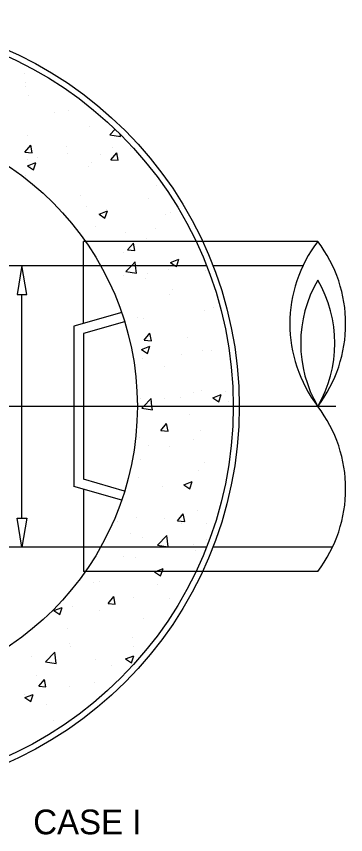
# Model space of a CAD drawing. Extents: x 6712067 to 6713867, y 1867712 to 1869162.
# Drawn here: x 6712343.8 to 6712423.9, y 1867918.1 to 1868116.9 of the extents above; entities that cross this region are included whole.
import ezdxf

# ---------------------------------------------------------------- set-up
doc = ezdxf.new("R2010")
doc.units = 0
for name, color, linetype in [('G-MARK', 7, 'Continuous'), ('G-TEXT', 7, 'Continuous'), ('Misc CnstDet(22)', 7, 'Continuous')]:
    doc.layers.add(name, color=color, linetype=linetype)

msp = doc.modelspace()

# ---------------------------------------------------------------- linework, layer by layer
at = {"layer": 'G-MARK'}
msp.add_line((6712345.2, 1867994.97), (6712345.2, 1868049.33), dxfattribs=at)
at = {"layer": 'G-TEXT'}
for points in [[(6712344.03, 1868049.33), (6712346.36, 1868049.33), (6712345.2, 1868056.33)], [(6712344.03, 1867994.97), (6712346.36, 1867994.97), (6712345.2, 1867987.98)]]:
    msp.add_lwpolyline(points, close=True, dxfattribs=at)
at = {"layer": 'Misc CnstDet(22)'}
for p, q in [((6712345.77, 1868103.12), (6712345.77, 1868103.12)), ((6712346.17, 1868100.93), (6712346.17, 1868100.93)), ((6712346.09, 1868099.86), (6712346.09, 1868099.86)), ((6712346.86, 1868097.56), (6712346.86, 1868097.56)), ((6712353.08, 1868093.46), (6712353.08, 1868093.46)), ((6712356.51, 1868094.06), (6712356.51, 1868094.06)), ((6712361.66, 1868090.04), (6712361.66, 1868090.04)), ((6712366.58, 1868088.11), (6712367.86, 1868089.46)), ((6712369.17, 1868087.71), (6712369.1, 1868088.25)), ((6712346.51, 1868087.86), (6712346.51, 1868087.86)), ((6712366.58, 1868088.11), (6712369.17, 1868087.71)), ((6712345.92, 1868083.89), (6712347.33, 1868085.57)), ((6712347.67, 1868083.74), (6712347.33, 1868085.57)), ((6712356.06, 1868085.38), (6712356.06, 1868085.38)), ((6712367.19, 1868084.97), (6712367.19, 1868084.97)), ((6712371.62, 1868084.73), (6712371.62, 1868084.73)), ((6712345.92, 1868083.89), (6712347.67, 1868083.74)), ((6712348.85, 1868082.56), (6712348.85, 1868082.56)), ((6712356.15, 1868083.51), (6712356.15, 1868083.51)), ((6712364.21, 1868083.26), (6712364.21, 1868083.26)), ((6712366.83, 1868082.07), (6712368.24, 1868083.74)), ((6712368.58, 1868081.92), (6712368.23, 1868083.74)), ((6712346.53, 1868080.56), (6712348.57, 1868081.35)), ((6712346.53, 1868080.56), (6712347.98, 1868079.59)), ((6712346.65, 1868082.12), (6712346.65, 1868082.12)), ((6712347.21, 1868080.34), (6712347.21, 1868080.34)), ((6712347.98, 1868079.59), (6712348.57, 1868081.34)), ((6712361.3, 1868080.34), (6712361.3, 1868080.34)), ((6712362.21, 1868081.47), (6712362.21, 1868081.47)), ((6712366.83, 1868082.07), (6712368.58, 1868081.92)), ((6712346.15, 1868078.15), (6712346.15, 1868078.15)), ((6712377.93, 1868075.9), (6712377.93, 1868075.9)), ((6712359.52, 1868073.47), (6712359.52, 1868073.47)), ((6712375.91, 1868072.69), (6712375.91, 1868072.69)), ((6712360.94, 1868070.64), (6712360.94, 1868070.64)), ((6712363.93, 1868068.83), (6712365.97, 1868069.61)), ((6712363.93, 1868068.83), (6712365.37, 1868067.85)), ((6712365.37, 1868067.85), (6712365.97, 1868069.61)), ((6712365.82, 1868069.91), (6712365.82, 1868069.91)), ((6712380.01, 1868068.79), (6712380.01, 1868068.79)), ((6712381.38, 1868069.25), (6712381.38, 1868069.25)), ((6712363.01, 1868065.87), (6712363.01, 1868065.87)), ((6712370.26, 1868064.4), (6712370.26, 1868064.4)), ((6712377.55, 1868065.36), (6712377.55, 1868065.36)), ((6712375.55, 1868062.98), (6712375.55, 1868062.98)), ((6712386.99, 1868062.38), (6712386.99, 1868062.38)), ((6712360.13, 1868042.27), (6712360.13, 1868062.22)), ((6712389.13, 1868062.22), (6712360.13, 1868062.22)), ((6712370.87, 1868060.15), (6712372.28, 1868061.81)), ((6712372.62, 1868059.99), (6712372.28, 1868061.81)), ((6712417.12, 1868062.22), (6712389.13, 1868062.22)), ((6712369.99, 1868059.47), (6712369.99, 1868059.47)), ((6712370.87, 1868060.15), (6712372.62, 1868059.99)), ((6712371.81, 1868056.32), (6712372.72, 1868057.27)), ((6712372.82, 1868056.32), (6712372.71, 1868057.27)), ((6712381.33, 1868057.09), (6712383.37, 1868057.87)), ((6712381.33, 1868057.09), (6712382.46, 1868056.32)), ((6712382.85, 1868056.32), (6712383.37, 1868057.87)), ((6712364.34, 1868056.32), (6712242.25, 1868056.32)), ((6712345.2, 1868056.33), (6712345.2, 1868056.33)), ((6712345.2, 1868056.33), (6712345.2, 1868056.33)), ((6712390.08, 1868056.32), (6712364.34, 1868056.32)), ((6712370.45, 1868054.9), (6712371.81, 1868056.32)), ((6712370.45, 1868054.9), (6712373.04, 1868054.5)), ((6712373.04, 1868054.49), (6712372.82, 1868056.32)), ((6712380.92, 1868055.31), (6712380.92, 1868055.31)), ((6712382.46, 1868056.32), (6712382.78, 1868056.12)), ((6712382.77, 1868056.12), (6712382.85, 1868056.32)), ((6712389.92, 1868055.14), (6712389.92, 1868055.14)), ((6712413.53, 1868056.32), (6712391.65, 1868056.32)), ((6712369.88, 1868053.87), (6712369.88, 1868053.87)), ((6712375.2, 1868053.28), (6712375.2, 1868053.28)), ((6712375.7, 1868054.35), (6712375.7, 1868054.35)), ((6712381.85, 1868050.44), (6712381.85, 1868050.44)), ((6712381.12, 1868049.27), (6712381.12, 1868049.27)), ((6712369.44, 1868044.93), (6712357.8, 1868041.6)), ((6712389.57, 1868045.45), (6712389.57, 1868045.45)), ((6712391.67, 1868046.25), (6712391.67, 1868046.25)), ((6712370.16, 1868042.71), (6712360.14, 1868039.85)), ((6712373.26, 1868043.82), (6712373.26, 1868043.82)), ((6712374.84, 1868043.58), (6712374.84, 1868043.58)), ((6712357.8, 1868041.6), (6712357.8, 1868002.69)), ((6712360.14, 1868039.85), (6712360.14, 1868004.45)), ((6712374.92, 1868038.22), (6712376.32, 1868039.89)), ((6712376.67, 1868038.06), (6712376.32, 1868039.89)), ((6712385.47, 1868038.88), (6712385.47, 1868038.88)), ((6712374.23, 1868035.95), (6712376.28, 1868036.74)), ((6712374.92, 1868038.22), (6712376.67, 1868038.07)), ((6712375.68, 1868034.98), (6712376.28, 1868036.74)), ((6712374.23, 1868035.95), (6712375.69, 1868034.98)), ((6712384, 1868034.75), (6712384, 1868034.75)), ((6712389.21, 1868035.74), (6712389.21, 1868035.74)), ((6712391.3, 1868035.71), (6712391.3, 1868035.71)), ((6712374.49, 1868033.88), (6712374.49, 1868033.88)), ((6712379.93, 1868031.88), (6712379.93, 1868031.88)), ((6712386.9, 1868025.48), (6712386.9, 1868025.48)), ((6712388.85, 1868026.04), (6712388.85, 1868026.04)), ((6712391.63, 1868024.22), (6712393.67, 1868025.01)), ((6712393.09, 1868023.24), (6712393.67, 1868025.01)), ((6712394.67, 1868025.66), (6712394.67, 1868025.66)), ((6712374.13, 1868024.17), (6712374.13, 1868024.17)), ((6712374.76, 1868022.15), (6712376.57, 1868024.04)), ((6712376.33, 1868023.25), (6712376.33, 1868023.25)), ((6712376.79, 1868022.15), (6712376.57, 1868024.04)), ((6712379.79, 1868023.99), (6712379.79, 1868023.99)), ((6712383.63, 1868024.22), (6712383.63, 1868024.22)), ((6712391.63, 1868024.22), (6712393.09, 1868023.24)), ((6712395.35, 1868023.33), (6712395.35, 1868023.33)), ((6712421.49, 1868022.15), (6712182.32, 1868022.15)), ((6712374.3, 1868021.68), (6712374.76, 1868022.15)), ((6712374.3, 1868021.68), (6712376.9, 1868021.28)), ((6712376.9, 1868021.28), (6712376.79, 1868022.15)), ((6712385.94, 1868020.07), (6712385.94, 1868020.07)), ((6712378.96, 1868016.29), (6712380.37, 1868017.96)), ((6712380.71, 1868016.14), (6712380.37, 1868017.96)), ((6712378.96, 1868016.29), (6712380.71, 1868016.14)), ((6712388.51, 1868016.33), (6712388.51, 1868016.33)), ((6712373.79, 1868014.47), (6712373.79, 1868014.47)), ((6712375.95, 1868012.72), (6712375.95, 1868012.72)), ((6712386.99, 1868014.17), (6712386.99, 1868014.17)), ((6712381.04, 1868012.36), (6712381.04, 1868012.36)), ((6712373.99, 1868009.17), (6712373.99, 1868009.17)), ((6712389.55, 1868008.52), (6712389.55, 1868008.52)), ((6712373.43, 1868004.76), (6712373.43, 1868004.76)), ((6712388.15, 1868006.63), (6712388.15, 1868006.63)), ((6712370.16, 1868001.58), (6712360.14, 1868004.45)), ((6712384.54, 1868003.09), (6712386.58, 1868003.87)), ((6712384.54, 1868003.09), (6712386, 1868002.1)), ((6712386, 1868002.1), (6712386.58, 1868003.87)), ((6712369.44, 1867999.37), (6712357.8, 1868002.69)), ((6712360.13, 1868002.02), (6712360.13, 1867982.06)), ((6712379.33, 1868002.67), (6712379.33, 1868002.67)), ((6712387.8, 1867996.93), (6712387.8, 1867996.93)), ((6712373.07, 1867995.05), (6712373.07, 1867995.05)), ((6712379.83, 1867994.96), (6712379.83, 1867994.96)), ((6712383.01, 1867994.37), (6712384.41, 1867996.04)), ((6712384.76, 1867994.21), (6712384.41, 1867996.04)), ((6712368.31, 1867994.27), (6712368.31, 1867994.27)), ((6712383.01, 1867994.37), (6712384.76, 1867994.22)), ((6712383.87, 1867993.62), (6712383.87, 1867993.62)), ((6712390.07, 1867993.6), (6712390.07, 1867993.6)), ((6712371.66, 1867991.18), (6712371.66, 1867991.18)), ((6712378.17, 1867988.46), (6712380.44, 1867990.82)), ((6712380.76, 1867988.05), (6712380.44, 1867990.82)), ((6712374.46, 1867990.36), (6712374.46, 1867990.36)), ((6712390.02, 1867989.71), (6712390.02, 1867989.71)), ((6712364.34, 1867987.97), (6712242.25, 1867987.97)), ((6712345.2, 1867987.98), (6712345.2, 1867987.98)), ((6712390.08, 1867987.97), (6712364.34, 1867987.97)), ((6712378.17, 1867988.46), (6712380.76, 1867988.05)), ((6712386.82, 1867988.57), (6712386.82, 1867988.57)), ((6712387.44, 1867987.23), (6712387.44, 1867987.23)), ((6712420.72, 1867987.97), (6712391.65, 1867987.97)), ((6712369.82, 1867985.64), (6712369.82, 1867985.64)), ((6712372.72, 1867985.36), (6712372.72, 1867985.36)), ((6712389.13, 1867982.06), (6712360.13, 1867982.06)), ((6712377.45, 1867981.95), (6712377.77, 1867982.06)), ((6712377.45, 1867981.95), (6712378.9, 1867980.96)), ((6712377.77, 1867982.06), (6712379.49, 1867982.73)), ((6712378.9, 1867980.96), (6712379.27, 1867982.06)), ((6712379.27, 1867982.06), (6712379.49, 1867982.73)), ((6712382.4, 1867982.1), (6712382.4, 1867982.1)), ((6712417.12, 1867982.06), (6712389.13, 1867982.06)), ((6712362.52, 1867979.46), (6712362.52, 1867979.46)), ((6712364, 1867979.68), (6712364, 1867979.68)), ((6712378.08, 1867978.8), (6712378.08, 1867978.8)), ((6712366.14, 1867974.27), (6712367.55, 1867975.95)), ((6712367.89, 1867974.11), (6712367.55, 1867975.94)), ((6712372.36, 1867975.65), (6712372.36, 1867975.65)), ((6712380.95, 1867975.45), (6712380.95, 1867975.45)), ((6712352.96, 1867972.54), (6712355, 1867973.33)), ((6712354.4, 1867971.56), (6712355, 1867973.33)), ((6712357.4, 1867973.61), (6712357.4, 1867973.61)), ((6712366.14, 1867974.27), (6712367.89, 1867974.11)), ((6712352.96, 1867972.54), (6712354.4, 1867971.56)), ((6712363.95, 1867972.53), (6712363.95, 1867972.53)), ((6712374.74, 1867970.61), (6712374.74, 1867970.61)), ((6712356.33, 1867968.18), (6712356.33, 1867968.18)), ((6712372.01, 1867965.95), (6712372.01, 1867965.95)), ((6712356.84, 1867964.56), (6712356.84, 1867964.56)), ((6712357.04, 1867963.9), (6712357.04, 1867963.9)), ((6712372.4, 1867963.91), (6712372.4, 1867963.91)), ((6712347.43, 1867961.3), (6712347.43, 1867961.3)), ((6712350.93, 1867960.06), (6712353.2, 1867962.43)), ((6712353.52, 1867959.66), (6712353.2, 1867962.43)), ((6712370.35, 1867960.81), (6712372.4, 1867961.59)), ((6712371.81, 1867959.82), (6712372.4, 1867961.59)), ((6712350.93, 1867960.06), (6712353.52, 1867959.66)), ((6712362.99, 1867960.65), (6712362.99, 1867960.65)), ((6712367.07, 1867959.11), (6712367.07, 1867959.11)), ((6712370.35, 1867960.81), (6712371.81, 1867959.83)), ((6712348.65, 1867956.69), (6712348.65, 1867956.69)), ((6712349.28, 1867954.17), (6712350.68, 1867955.84)), ((6712351.03, 1867954.02), (6712350.68, 1867955.84)), ((6712362.75, 1867955.14), (6712362.75, 1867955.14)), ((6712349.28, 1867954.17), (6712351.03, 1867954.02)), ((6712356.69, 1867954.19), (6712356.69, 1867954.19)), ((6712345.75, 1867952.21), (6712345.75, 1867952.21)), ((6712345.86, 1867951.41), (6712347.91, 1867952.19)), ((6712345.86, 1867951.41), (6712347.31, 1867950.42)), ((6712347.31, 1867950.42), (6712347.91, 1867952.19)), ((6712351.04, 1867949.75), (6712351.04, 1867949.75)), ((6712352.74, 1867945.82), (6712352.74, 1867945.82))]:
    msp.add_line(p, q, dxfattribs=at)
msp.add_lwpolyline([(6712417.12, 1868022.15), (6712417.12, 1868022.15)], dxfattribs=at)
for radius in [94.73, 93.28, 69.96]:
    msp.add_circle((6712303.29, 1868022.15), radius, dxfattribs=at)
for centre, radius, start, end in [((6712443.36, 1868042.19), 33.02, 142.6308, 217.3692), ((6712390.88, 1868042.19), 33.02, 322.6308, 37.3692), ((6712443.36, 1868037.47), 30.39, 149.7116, 210.2885), ((6712390.88, 1868037.47), 30.39, 329.7116, 30.2885), ((6712390.88, 1868002.11), 33.02, 322.6308, 37.3692)]:
    msp.add_arc(centre, radius, start, end, dxfattribs=at)

# ---------------------------------------------------------------- texts
msp.add_text('CASE I', height=6, dxfattribs=at).set_placement((6712347.93, 1867918.2))

doc.saveas('drawing.dxf')
